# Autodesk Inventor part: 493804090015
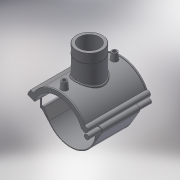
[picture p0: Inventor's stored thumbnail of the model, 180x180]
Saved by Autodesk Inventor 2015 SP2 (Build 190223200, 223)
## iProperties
Created: 2017-07
Part Number: 493804090015
Material: Generic
Description: PLASSON TRANSITION SADDLE 90-1.1/2"
Document SubType Name: Modeling
Designer: KIM
Density: 1 g/cm^3
Appearance: Default
Author: KIM
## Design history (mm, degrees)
derived "493804.ipt"
feature "Solid1::493804.ipt"
tag "TaggingFeature1"
body "Solid1"
other parameters: "d1" = 109.8, "d2" = 121, "d3" = 22.5, "d4" = 118, "d5" = 0, "d6" = 0.1, "d8" = 0, "d19" = 6, "d20" = 6, "d21" = 70.8, "d23" = 0, "d24" = 35.4, "d26" = 0, "d27" = 3, "d28" = 3, "d29" = 3, "d31" = 6, "d32" = 0, "d33" = 0, "d34" = 0.6, "d40" = 57.096, "d41" = 62.783, "d43" = 0, "d45" = 0, "d47" = 107.9, "d48" = 58.2985, "d50" = 0, "d70" = 15, "d72" = 0, "d73" = 6, "d75" = 5, "d76" = 0, "d77" = 4.5, "d78" = 75, "d79" = 15, "d80" = 47.2, "d82" = 5 deg, "d84" = 4, "d85" = 14, "d86" = 0, "d87" = 3, "d88" = 0, "d89" = 1, "d90" = 1, "d91" = 94.4, "d92" = 0, "d93" = 0.5, "d94" = 47.36842, "d96" = 111.996, "d97" = 2.36, "d98" = 0, "d102" = 1.34535, "d103" = 44.845, "d104" = 31.8, "d105" = 0, "d106" = 35.876, "d108" = 0, "d109" = -17.66667, "d111" = 0.5, "d112" = 0.5, "d113" = 0, "d114" = 0.5, "d117" = 0.44845, "d120" = 140 deg, "d121" = 24.228, "d122" = 20 deg, "d123" = 219.6, "d124" = 65.88, "d126" = 0, "d143" = 92.7, "d145" = 15.23077, "d149" = 1.35, "d150" = 16.75385, "d153" = 118, "d154" = 0, "d156" = 54.9, "d157" = 160 deg, "d159" = 3.96, "d161" = 1.35, "d162" = 70.8, "d163" = 0, "d164" = 45, "d167" = 9, "d168" = 53.56098, "d170" = 2.1, "d172" = 0, "d173" = 1, "d175" = 45, "d176" = 20 deg, "d177" = 6.3, "d178" = 19.8, "d180" = 0, "d183" = 7.92, "d184" = 5.04, "d185" = 38.35, "d186" = 38.35, "d187" = 54.9, "d188" = 5.94, "d189" = 6.3, "d190" = 0, "d191" = 65.88, "d193" = 4.2, "d194" = 2.95, "d195" = 90 deg, "d197" = 0, "d199" = 0, "B_" = 121, "H_" = 53, "L_" = 118, "d_t" = 6, "G_" = 44.845, "d148" = 1.35, "d160" = 1.35, "d169" = 2.1, "d192" = 4.2
